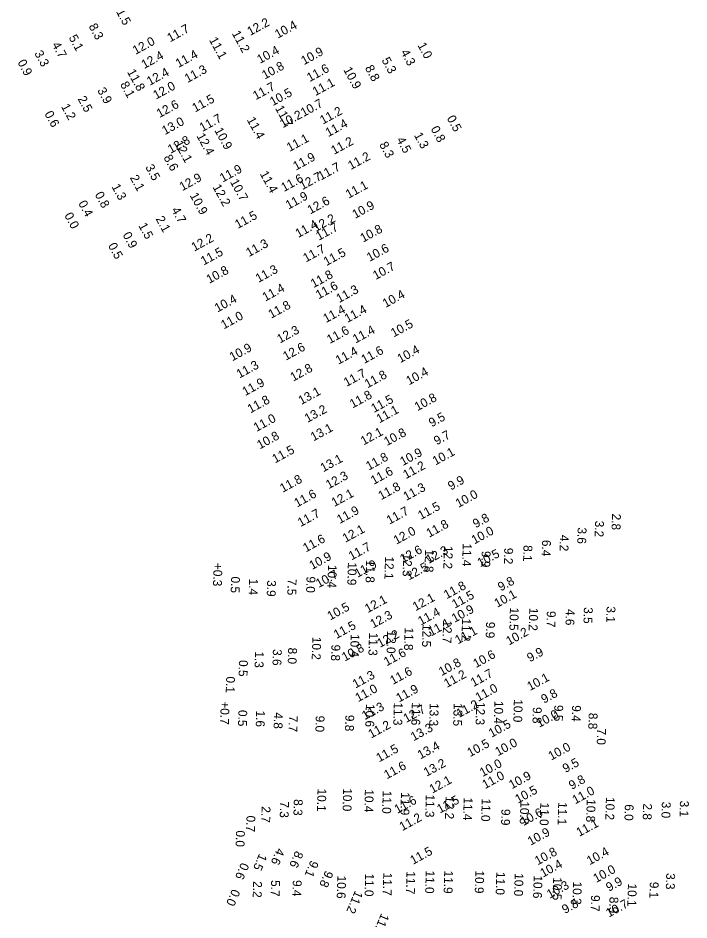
# Model space of a CAD drawing. Extents: x 815385 to 820851, y 582449 to 604245.
# Drawn here: x 817762 to 818141, y 600273 to 600781 of the extents above; entities that cross this region are included whole.
import ezdxf

# ---------------------------------------------------------------- set-up
doc = ezdxf.new("R2010")
doc.units = 0
for name, color, linetype in [('V-TOPO-SOUN-021909', 7, 'Continuous'), ('V-TOPO-SOUN-022409', 7, 'Continuous'), ('V-TOPO-SOUN-EXCSS', 7, 'Continuous')]:
    doc.layers.add(name, color=color, linetype=linetype)

msp = doc.modelspace()

# ---------------------------------------------------------------- texts
at = {"layer": 'V-TOPO-SOUN-021909'}
for s, rotation, p in [('3.2', 268.338, (818087.68, 600497.81)), ('2.8', 268.338, (818097.22, 600501.79)), ('3.6', 268.338, (818077.87, 600494.03)), ('4.2', 268.338, (818067.89, 600489.86)), ('12.2 ', 268.338, (818002.54, 600483.58)), ('11.4 ', 268.338, (818013.11, 600485.03)), ('9.2', 268.338, (818036.52, 600482.52)), ('8.1', 268.338, (818047.36, 600484.03)), ('6.4', 268.338, (818057.83, 600486.97)), ('12.1 ', 268.338, (817969.33, 600477.67)), ('12.3 ', 268.338, (817979.56, 600479.32)), ('12.8 ', 268.338, (817991.89, 600481.6)), ('9.9', 268.338, (818023.79, 600480.75)), ('+0.3 ', 268.338, (817872.7, 600474.01)), ('10.4 ', 268.338, (817937.16, 600472.88)), ('10.9 ', 268.338, (817948.39, 600474.34)), ('11.8 ', 268.338, (817958.7, 600475.76)), ('0.5', 268.338, (817882.57, 600466.31)), ('1.4', 268.338, (817892.75, 600465.14)), ('3.9', 268.338, (817902.9, 600464.29)), ('7.5', 268.338, (817914.46, 600465.01)), ('9.0', 268.338, (817925.08, 600466.4)), ('10.5 ', 268.338, (818039.69, 600448.84)), ('10.2 ', 268.338, (818050.59, 600448.68)), ('4.6', 268.338, (818071.23, 600448.02)), ('3.5', 268.338, (818081.39, 600449.03)), ('3.1', 268.338, (818094.18, 600449.52)), ('11.2 ', 268.338, (818012.72, 600442.7)), ('9.7', 268.338, (818060.52, 600446.91)), ('11.8 ', 268.338, (817980.39, 600437.61)), ('12.5 ', 268.338, (817990.47, 600439.5)), ('12.7 ', 268.338, (818002.05, 600441.62)), ('9.9', 268.338, (818026.27, 600440.8)), ('10.2 ', 268.338, (817928.36, 600432.34)), ('10.4 ', 268.338, (817949.95, 600433.89)), ('11.3 ', 268.338, (817960.3, 600434.68)), ('12.0 ', 268.338, (817970.53, 600435.88)), ('9.8', 268.338, (817939.11, 600427.97)), ('1.3', 268.338, (817896.04, 600424.12)), ('3.6', 268.338, (817906.14, 600425.39)), ('8.0', 268.338, (817914.72, 600426.25)), ('0.5', 268.338, (817887.01, 600419.22)), ('0.1', 268.338, (817879.8, 600409.97)), ('10.4 ', 268.338, (818030.99, 600396.19)), ('10.0 ', 268.338, (818041.93, 600397.11)), ('+0.7 ', 268.338, (817876.72, 600395.97)), ('0.5', 268.338, (817886.68, 600391.09)), ('10.6 ', 268.338, (817958.54, 600394.45)), ('11.3 ', 268.338, (817974.3, 600395.35)), ('11.6 ', 268.338, (817984.44, 600395.4)), ('13.3 ', 268.338, (817994.56, 600394.97)), ('13.5 ', 268.338, (818008.04, 600394.95)), ('12.3 ', 268.338, (818020.69, 600395.57)), ('9.8', 268.338, (818052.64, 600392.72)), ('9.5', 268.338, (818064.71, 600393.93)), ('9.4', 268.338, (818074.74, 600393.78)), ('1.6', 268.338, (817896.7, 600390.76)), ('4.8', 268.338, (817906.77, 600389.71)), ('7.7', 268.338, (817915.14, 600387.89)), ('9.0', 268.338, (817930.28, 600387.89)), ('9.8', 268.338, (817946.96, 600388.33)), ('8.8', 268.338, (818084.1, 600389.46)), ('7.0', 268.338, (818088.83, 600380.68)), ('10.1 ', 268.338, (817931.29, 600346.76)), ('10.0 ', 268.338, (817945.74, 600346.95)), ('10.4 ', 268.338, (817957.97, 600346.32)), ('11.0 ', 268.338, (817968.04, 600345.58)), ('8.3', 268.338, (817917.94, 600340.78)), ('11.9 ', 268.338, (817978.32, 600344.7)), ('11.3 ', 268.338, (817992.31, 600343.46)), ('12.2 ', 268.338, (818003.43, 600342.49)), ('11.4 ', 268.338, (818013.67, 600341.77)), ('11.0 ', 268.338, (818023.83, 600341.19)), ('10.8 ', 268.338, (818082.98, 600340.8)), ('10.2 ', 268.338, (818093.79, 600341.99)), ('2.7', 268.338, (817899.78, 600336.77)), ('7.3', 268.338, (817910.22, 600339.55)), ('9.9', 268.338, (818034.9, 600335.26)), ('10.8 ', 268.338, (818045.58, 600339.6)), ('11.0 ', 268.338, (818056.78, 600338.88)), ('11.1 ', 268.338, (818066.92, 600339.13)), ('6.0', 268.338, (818104.44, 600337.92)), ('2.8', 268.338, (818114.79, 600338.38)), ('3.0', 268.338, (818125.31, 600339.37)), ('3.1', 268.338, (818135.52, 600339.96)), ('0.7', 268.338, (817891.24, 600331.54)), ('0.0', 268.338, (817885.35, 600323.14)), ('1.5', 246.933, (817898.46, 600310.35)), ('4.6', 246.933, (817908.46, 600313.52)), ('8.6', 246.933, (817918.87, 600311.92)), ('0.6', 246.933, (817888.31, 600305.3)), ('9.1', 246.933, (817927.51, 600306.55)), ('9.8', 246.933, (817935.77, 600300.84)), ('11.7 ', 268.338, (817981.43, 600300.14)), ('11.0 ', 268.338, (817992.28, 600300.56)), ('11.9 ', 268.338, (818002.68, 600300.53)), ('10.9 ', 268.338, (818020.22, 600300.62)), ('11.0 ', 268.338, (818031.99, 600299.78)), ('2.2', 268.338, (817895.01, 600294.53)), ('5.7', 268.338, (817905.11, 600295.16)), ('9.4', 268.338, (817917.38, 600295.19)), ('10.6 ', 268.338, (817942.42, 600297.7)), ('11.0 ', 268.338, (817958.13, 600298.92)), ('11.7 ', 268.338, (817968.33, 600299.37)), ('10.0 ', 268.338, (818042.37, 600299.05)), ('10.6 ', 268.338, (818053.07, 600297.8)), ('10.5 ', 268.338, (818064.08, 600296.76)), ('3.3', 268.338, (818127.78, 600299.12)), ('0.0', 246.933, (817883.26, 600290.41)), ('11.2 ', 246.933, (817952.49, 600289.52)), ('10.3 ', 268.338, (818075.24, 600294.33)), ('10.1 ', 268.338, (818106.19, 600293.23)), ('9.1', 268.338, (818118.52, 600294.19)), ('9.7', 268.338, (818085.41, 600286.71)), ('8.9', 268.338, (818095.81, 600285.72)), ('11.0 ', 246.933, (817967.27, 600276.69))]:
    msp.add_text(s, height=5, rotation=rotation, dxfattribs=at).set_placement(p)
at = {"layer": 'V-TOPO-SOUN-022409'}
for s, rotation, p in [('11.5 ', 298.553, (817815.83, 600788.02)), ('8.3', 298.553, (817802.14, 600776.52)), ('11.7 ', 28.553, (817848.15, 600767.41)), ('12.2 ', 28.553, (817893.28, 600771.02)), ('10.4 ', 28.553, (817908.84, 600769.49)), ('5.1', 298.553, (817790.91, 600770.16)), ('11.2 ', 298.553, (817882.84, 600772.5)), ('12.0 ', 28.553, (817828.73, 600760.38)), ('11.1 ', 298.553, (817870, 600768.86)), ('1.0', 298.553, (817987.47, 600765.83)), ('3.3', 298.553, (817771.54, 600761.29)), ('4.7', 298.553, (817781.4, 600766.15)), ('12.4 ', 28.553, (817833.6, 600752.4)), ('11.4 ', 28.553, (817852.91, 600753.01)), ('10.4 ', 28.553, (817898.81, 600755.28)), ('10.9 ', 28.553, (817923.63, 600754.55)), ('4.3', 298.553, (817977.97, 600761.85)), ('0.9', 298.553, (817762.05, 600756.2)), ('5.3', 298.553, (817967.23, 600757.42)), ('11.8 ', 298.553, (817823.8, 600750.82)), ('12.4 ', 28.553, (817836.71, 600742.92)), ('11.3 ', 28.553, (817858, 600744.49)), ('10.8 ', 28.553, (817901.55, 600746.45)), ('11.6 ', 28.553, (817926.89, 600745.03)), ('10.9 ', 298.553, (817945.67, 600752.03)), ('8.8', 298.553, (817957.83, 600753.02)), ('11.1 ', 28.553, (817930.1, 600737.12)), ('3.9', 298.553, (817807, 600740.42)), ('8.1', 298.553, (817819.86, 600743.79)), ('12.0 ', 28.553, (817840.25, 600735.15)), ('11.7 ', 28.553, (817896.45, 600734.78)), ('10.5 ', 28.553, (817906.03, 600731.43)), ('2.5', 298.553, (817795.93, 600735.65)), ('11.5 ', 28.553, (817862.26, 600727.88)), ('1.2', 298.553, (817786.62, 600731.27)), ('12.6 ', 28.553, (817842.21, 600724.76)), ('11.7 ', 298.553, (817907.21, 600730.34)), ('10.7 ', 28.553, (817923.37, 600725.3)), ('0.6', 298.553, (817777.25, 600727.18)), ('11.7 ', 28.553, (817866.35, 600716.87)), ('11.2 ', 28.553, (817934.26, 600721.04)), ('0.5', 298.553, (818003.95, 600724.68)), ('13.0 ', 28.553, (817845.22, 600715.11)), ('11.4 ', 298.553, (817891.29, 600723.8)), ('11.4 ', 28.553, (817937.34, 600714)), ('12.4 ', 298.553, (817862.9, 600714.72)), ('10.9 ', 298.553, (817872.99, 600717.87)), ('1.3', 298.553, (817985.48, 600715.11)), ('0.8', 298.553, (817994.86, 600718.67)), ('12.1 ', 298.553, (817850.48, 600710.48)), ('11.1 ', 28.553, (817915.5, 600705.64)), ('11.2 ', 28.553, (817940.55, 600703.97)), ('8.3', 298.553, (817965.89, 600709.84)), ('4.5', 298.553, (817975.6, 600712.57)), ('8.6', 298.553, (817844.36, 600702.52)), ('11.9 ', 28.553, (817919.1, 600695.1)), ('11.2 ', 28.553, (817950.05, 600695.44)), ('3.5', 298.553, (817834.06, 600697.11)), ('11.9 ', 28.553, (817877.8, 600688.37)), ('11.7 ', 28.553, (817933.17, 600689.5)), ('2.1', 298.553, (817825.38, 600691.17)), ('12.9 ', 28.553, (817855.06, 600683.51)), ('11.4 ', 298.553, (817898.6, 600693.38)), ('11.6 ', 28.553, (817912.37, 600683.04)), ('1.3', 298.553, (817815.05, 600686.09)), ('12.2 ', 298.553, (817871.98, 600685.89)), ('10.7 ', 298.553, (817881.82, 600688.8)), ('11.1 ', 28.553, (817948.77, 600679.24)), ('0.8', 298.553, (817805.62, 600681.65)), ('10.9 ', 298.553, (817859.13, 600681.13)), ('11.9 ', 28.553, (817914.91, 600673.11)), ('12.6 ', 28.553, (817927.19, 600670.39)), ('0.4', 298.553, (817796.27, 600676.71)), ('10.9 ', 28.553, (817952.46, 600667.9)), ('0.0', 298.553, (817788.4, 600669.9)), ('4.7', 298.553, (817848.75, 600673)), ('11.5 ', 28.553, (817886.33, 600662.2)), ('1.5', 298.553, (817830.18, 600664.12)), ('2.1', 298.553, (817839.91, 600667.94)), ('11.4 ', 28.553, (817920.42, 600657.1)), ('11.7 ', 28.553, (817931.99, 600655.55)), ('0.9', 298.553, (817821.27, 600658.92)), ('10.8 ', 28.553, (817956.96, 600654.52)), ('12.2 ', 28.553, (817861.8, 600649.41)), ('11.3 ', 28.553, (817892.58, 600646.34)), ('0.5', 298.553, (817813.06, 600652.86)), ('11.5 ', 28.553, (817867.11, 600641.59)), ('11.7 ', 28.553, (817924.74, 600643.31)), ('11.5 ', 28.553, (817936.29, 600641.26)), ('10.6 ', 28.553, (817960.62, 600643.66)), ('10.8 ', 28.553, (817870.25, 600631.26)), ('11.3 ', 28.553, (817897.99, 600631.8)), ('10.7 ', 28.553, (817964.07, 600633.42)), ('11.8 ', 28.553, (817929.02, 600628.83)), ('11.4 ', 28.553, (817901.83, 600621.24)), ('11.6 ', 28.553, (817931.87, 600622.51)), ('11.3 ', 28.553, (817943.46, 600620.41)), ('10.4 ', 28.553, (817874.9, 600615.09)), ('10.4 ', 28.553, (817969.57, 600617.66)), ('11.8 ', 28.553, (817905.18, 600611.6)), ('11.0 ', 28.553, (817878.46, 600605.57)), ('11.4 ', 28.553, (817936.03, 600609.13)), ('11.4 ', 28.553, (817948.1, 600609.2)), ('10.5 ', 28.553, (817974.18, 600601.04)), ('12.3 ', 28.553, (817910.06, 600597.59)), ('11.6 ', 28.553, (817938.17, 600597.33)), ('11.4 ', 28.553, (817952.73, 600597.62)), ('10.9 ', 28.553, (817883.29, 600587.58)), ('12.6 ', 28.553, (817913.42, 600587.93)), ('11.4 ', 28.553, (817943.06, 600585.66)), ('11.6 ', 28.553, (817957.53, 600586.08)), ('10.4 ', 28.553, (817977.86, 600586.5)), ('11.3 ', 28.553, (817887.24, 600577.86)), ('12.8 ', 28.553, (817917.54, 600576.1)), ('10.4 ', 28.553, (817982.81, 600574.03)), ('11.7 ', 28.553, (817947.64, 600573.16)), ('11.8 ', 28.553, (817959.43, 600572.33)), ('11.9 ', 28.553, (817890.5, 600567.97)), ('13.1 ', 28.553, (817922.11, 600562.95)), ('11.8 ', 28.553, (817951.04, 600561)), ('11.5 ', 28.553, (817963.1, 600558.48)), ('10.8 ', 28.553, (817987.56, 600559.43)), ('11.8 ', 28.553, (817893.45, 600558.19)), ('13.2 ', 28.553, (817925.62, 600552.87)), ('11.1 ', 28.553, (817966.11, 600552.6)), ('9.5', 28.553, (817995.58, 600550.37)), ('11.0 ', 28.553, (817896.86, 600547.74)), ('13.1 ', 28.553, (817928.99, 600542.41)), ('12.1 ', 28.553, (817957.21, 600540.14)), ('10.8 ', 28.553, (817970.33, 600539.75)), ('9.7', 28.553, (817998.41, 600540.18)), ('10.8 ', 28.553, (817898.77, 600537.91)), ('11.5 ', 28.553, (817907.36, 600530)), ('10.9 ', 28.553, (817979.39, 600528.53)), ('10.1 ', 28.553, (817997.7, 600528.85)), ('13.1 ', 28.553, (817934.52, 600525.01)), ('11.8 ', 28.553, (817960.17, 600525.97)), ('11.6 ', 28.553, (817962.9, 600517.9)), ('11.2 ', 28.553, (817981.08, 600521.12)), ('11.8 ', 28.553, (817911.67, 600513.47)), ('12.3 ', 28.553, (817937.56, 600515.45)), ('9.9', 28.553, (818006.38, 600514.71)), ('11.8 ', 28.553, (817967.12, 600509.27)), ('11.3 ', 28.553, (817981.21, 600508.81)), ('11.6 ', 28.553, (817919.75, 600505.15)), ('12.1 ', 28.553, (817940.74, 600505.43)), ('10.0 ', 28.553, (818010.68, 600504.92)), ('11.5 ', 28.553, (817989.48, 600498.12)), ('11.7 ', 28.553, (817921.73, 600494.11)), ('11.9 ', 28.553, (817943.78, 600495.86)), ('11.7 ', 28.553, (817971.78, 600495.46)), ('11.8 ', 28.553, (817994.19, 600488.12)), ('9.8', 28.553, (818020.39, 600493.42)), ('12.1 ', 28.553, (817946.98, 600485.29)), ('12.0 ', 28.553, (817975.71, 600484.17)), ('10.0 ', 28.553, (818019.66, 600484.31)), ('11.6 ', 28.553, (817924.69, 600479.81)), ('11.7 ', 28.553, (817950.4, 600475.28)), ('10.9 ', 28.553, (817928.21, 600469.93)), ('11.8 ', 28.553, (818004.02, 600453.41)), ('9.8', 28.553, (818034.54, 600457.8)), ('11.5 ', 28.553, (818008.59, 600448.11)), ('10.1 ', 28.553, (818032.5, 600448.59)), ('10.5 ', 28.553, (817938.4, 600441.43)), ('12.1 ', 28.553, (817959.54, 600445.57)), ('12.1 ', 28.553, (817986.49, 600446.66)), ('12.3 ', 28.553, (817962.56, 600436.91)), ('11.4 ', 28.553, (817989.5, 600438.57)), ('10.9 ', 28.553, (818008.5, 600440.14)), ('11.5 ', 28.553, (817941.99, 600430.99)), ('9.9', 28.553, (818050.95, 600417.84)), ('10.6 ', 28.553, (818020.59, 600414.59)), ('10.8 ', 28.553, (818001.2, 600410.07)), ('11.3 ', 28.553, (817952.64, 600403.06)), ('11.6 ', 28.553, (817973.73, 600405.1)), ('11.2 ', 28.553, (818004.13, 600403.39)), ('11.7 ', 28.553, (818019.16, 600403.9)), ('10.1 ', 28.553, (818050.99, 600401.65)), ('11.0 ', 28.553, (817954.14, 600395.36)), ('11.9 ', 28.553, (817977.19, 600395.19)), ('11.0 ', 28.553, (818021.87, 600395.59)), ('9.8', 28.553, (818058.87, 600394.5)), ('11.5 ', 28.553, (817965.94, 600361.45)), ('13.4 ', 28.553, (817989.26, 600363.12)), ('10.5 ', 28.553, (818017.24, 600364.39)), ('10.0 ', 28.553, (818032.96, 600364.87)), ('10.0 ', 28.553, (818062.95, 600362.43)), ('11.6 ', 28.553, (817970.33, 600351.87)), ('13.2 ', 28.553, (817992.68, 600353.31)), ('10.0 ', 28.553, (818024.28, 600353.14)), ('9.5', 28.553, (818071.01, 600355.42)), ('11.0 ', 28.553, (818025.68, 600346.34)), ('10.9 ', 28.553, (818040.73, 600346.25)), ('12.1 ', 28.553, (817995.92, 600343.83)), ('9.8', 28.553, (818074.5, 600345.92)), ('10.5 ', 28.553, (818044.24, 600338.19)), ('11.0 ', 28.553, (818076.47, 600337.75)), ('11.5 ', 28.553, (817985.09, 600303.69)), ('10.8 ', 28.553, (818055.3, 600303.35)), ('10.4 ', 28.553, (818084.6, 600303.43)), ('10.4 ', 28.553, (818058.33, 600296.46)), ('10.0 ', 28.553, (818088.27, 600293.43)), ('9.9', 28.553, (818095.44, 600288.44))]:
    msp.add_text(s, height=5, rotation=rotation, dxfattribs=at).set_placement(p)
at = {"layer": 'V-TOPO-SOUN-EXCSS'}
for s, p in [('10.2 ', (817911.68, 600718.98)), ('12.8 ', (817848.5, 600704.58)), ('12.7 ', (817922.72, 600684.11)), ('12.2 ', (817930.41, 600660.51)), ('12.6 ', (817979.36, 600473.68)), ('12.3 ', (817993.99, 600473.37)), ('10.5 ', (818022.96, 600471.43)), ('11.9 ', (817953.77, 600465.49)), ('12.5 ', (817982.73, 600464)), ('10.7 ', (817931.92, 600459.72)), ('11.1 ', (817995.24, 600432.42)), ('11.1 ', (818010.37, 600427.96)), ('10.2 ', (818039.14, 600427.33)), ('12.2 ', (817966.48, 600426.01)), ('10.8 ', (817946.61, 600418.28)), ('11.6 ', (817970.24, 600415.61)), ('11.2 ', (818011.09, 600386.51)), ('11.3 ', (817957.93, 600385.21)), ('12.7 ', (817981.23, 600383.66)), ('10.0 ', (818056.17, 600380.93)), ('10.5 ', (818029.34, 600375.34)), ('11.2 ', (817961.5, 600374.89)), ('13.3 ', (817985.38, 600373.32)), ('11.6 ', (817976.18, 600332.4)), ('11.5 ', (818000.21, 600332.56)), ('10.6 ', (818047.31, 600325.51)), ('11.2 ', (817979.01, 600322.66)), ('10.9 ', (818051.31, 600314.42)), ('11.1 ', (818078.73, 600319.43)), ('10.3 ', (818062.09, 600284.52)), ('9.8', (818070.66, 600275.94)), ('10.7 ', (818095.42, 600273.93))]:
    msp.add_text(s, height=5, rotation=28.553, dxfattribs=at).set_placement(p)

doc.saveas('drawing.dxf')
